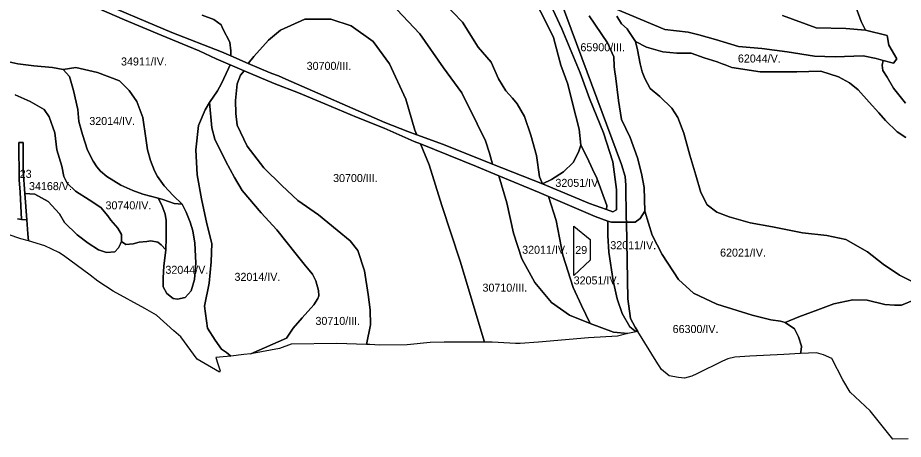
# Model space of a CAD drawing. Extents: x -521621 to -516761, y -1190184 to -1184927.
# Drawn here: x -520083 to -518423, y -1190183 to -1189393 of the extents above; entities that cross this region are included whole.
import ezdxf

# ---------------------------------------------------------------- set-up
doc = ezdxf.new("R2010")
doc.units = 0
doc.layers.add('BPEJ_s', color=7, linetype='Continuous')

msp = doc.modelspace()

# ---------------------------------------------------------------- linework, layer by layer
at = {"layer": 'BPEJ_s'}
for points in [[(-519063.9, -1189366), (-518997.4, -1189544), (-518951.2, -1189668.6), (-518944.3, -1189690.8), (-518943.5, -1189707.3), (-518942.3, -1189768.1), (-518942.1, -1189776.2), (-518970.3, -1189776.5), (-518977, -1189774.2), (-519000.8, -1189765.9), (-519088.4, -1189728.3), (-519105.4, -1189721), (-519181.4, -1189689.3), (-519222.8, -1189672.1), (-519328, -1189629.9), (-519339.7, -1189625.3), (-519396, -1189600.4), (-519447.8, -1189579.5), (-519507.3, -1189554.4), (-519556.5, -1189533.9), (-519601.9, -1189516.6), (-519658.2, -1189492.7), (-519684.5, -1189481.5), (-519711, -1189470.2), (-519742.7, -1189455.6), (-519813.9, -1189425.9), (-519882.5, -1189397.5), (-519948.9, -1189368.8)], [(-519944.2, -1189356.5), (-519794.2, -1189421.2), (-519701, -1189457.4), (-519683.6, -1189464.9), (-519650.9, -1189478.8), (-519610, -1189496.3), (-519597.8, -1189500.8), (-519594.3, -1189502.1), (-519580.6, -1189508.7), (-519394.8, -1189589.6), (-519351.9, -1189606.5), (-519335.1, -1189612.5), (-519284.9, -1189630.7), (-519192.9, -1189667.4), (-519099.2, -1189704.8), (-519011.2, -1189741.7), (-518979.4, -1189752.9), (-518967.9, -1189757), (-518960.6, -1189753.2), (-518960.6, -1189715.2), (-518967.9, -1189663.1), (-518985.2, -1189608.9), (-519011.6, -1189544.5), (-519028.8, -1189496.4), (-519062.9, -1189414.3), (-519083.6, -1189369.9)], [(-519736.9, -1189388.8), (-519715.2, -1189396.9), (-519701.7, -1189406.4), (-519698.2, -1189413.9), (-519685, -1189438.9), (-519683.3, -1189455.6), (-519683.6, -1189464.9), (-519701, -1189457.4), (-519794.2, -1189421.2), (-519944.2, -1189356.5)], [(-519383.2, -1189366.6), (-519329.3, -1189423.2), (-519284.6, -1189487.3), (-519250.7, -1189534.2), (-519222.1, -1189592.4), (-519206.5, -1189624.2), (-519198.4, -1189646.8), (-519192.9, -1189667.4), (-519284.9, -1189630.7), (-519335.1, -1189612.5), (-519338.8, -1189604.1), (-519355.5, -1189545.7), (-519386.1, -1189479.6), (-519416.7, -1189437.9), (-519457.7, -1189408.7), (-519495.9, -1189396.2), (-519544.6, -1189396.2), (-519590.1, -1189416.7), (-519612.7, -1189435.5), (-519640.2, -1189465.7), (-519650.9, -1189478.8), (-519683.6, -1189464.9), (-519683.3, -1189455.6), (-519685, -1189438.9), (-519698.2, -1189413.9), (-519701.7, -1189406.4), (-519715.2, -1189396.9), (-519736.9, -1189388.8)], [(-519285.7, -1189363.9), (-519249.6, -1189401.6), (-519220, -1189448.5), (-519195.7, -1189476.6), (-519181.7, -1189507.8), (-519168.3, -1189530.5), (-519155.7, -1189544.2), (-519146.9, -1189554.6), (-519133, -1189578.1), (-519121.4, -1189613.2), (-519110.7, -1189651.4), (-519105, -1189691.2), (-519099.2, -1189704.8), (-519192.9, -1189667.4), (-519198.4, -1189646.8), (-519206.5, -1189624.2), (-519222.1, -1189592.4), (-519250.7, -1189534.2), (-519284.6, -1189487.3), (-519329.3, -1189423.2), (-519383.2, -1189366.6)], [(-519118.6, -1189351), (-519094.8, -1189397.3), (-519078.9, -1189430.5), (-519070.3, -1189463.5), (-519065.2, -1189482), (-519052.1, -1189517.5), (-519042.9, -1189553.4), (-519030.6, -1189602), (-519027.8, -1189632.3), (-519032.2, -1189645.2), (-519041.9, -1189664.4), (-519060.3, -1189681.8), (-519082.8, -1189696.4), (-519099.2, -1189704.8), (-519105, -1189691.2), (-519110.7, -1189651.4), (-519121.4, -1189613.2), (-519133, -1189578.1), (-519146.9, -1189554.6), (-519155.7, -1189544.2), (-519168.3, -1189530.5), (-519181.7, -1189507.8), (-519195.7, -1189476.6), (-519220, -1189448.5), (-519249.6, -1189401.6), (-519285.7, -1189363.9)], [(-519083.6, -1189369.9), (-519062.9, -1189414.3), (-519028.8, -1189496.4), (-519011.6, -1189544.5), (-518985.2, -1189608.9), (-518967.9, -1189663.1), (-518960.6, -1189715.2), (-518960.6, -1189753.2), (-518967.9, -1189757), (-518979.4, -1189752.9), (-518978.8, -1189744.9), (-518997.8, -1189694.2), (-519005.4, -1189677), (-519015.4, -1189655), (-519027.8, -1189632.3), (-519030.6, -1189602), (-519042.9, -1189553.4), (-519052.1, -1189517.5), (-519065.2, -1189482), (-519070.3, -1189463.5), (-519078.9, -1189430.5), (-519094.8, -1189397.3), (-519118.6, -1189351)], [(-519011.7, -1189389.6), (-518977.5, -1189440.5), (-518965.9, -1189466.5), (-518965.2, -1189484.5), (-518963.7, -1189495), (-518962.4, -1189501.9), (-518957.2, -1189548.6), (-518951.6, -1189584.1), (-518935.3, -1189617.6), (-518921.4, -1189655.8), (-518913.8, -1189685.1), (-518909.1, -1189711.6), (-518907.7, -1189755.7), (-518916.4, -1189769.4), (-518925.9, -1189776.2), (-518942.1, -1189776.2), (-518942.3, -1189768.1), (-518943.5, -1189707.3), (-518944.3, -1189690.8), (-518951.2, -1189668.6), (-518997.4, -1189544), (-519063.9, -1189366)], [(-519948.9, -1189368.8), (-519882.5, -1189397.5), (-519813.9, -1189425.9), (-519742.7, -1189455.6), (-519711, -1189470.2), (-519684.5, -1189481.5), (-519687.6, -1189488.4), (-519700.6, -1189516.7), (-519708.6, -1189530.4), (-519723.2, -1189552), (-519731.6, -1189565.9), (-519744.1, -1189595.1), (-519748.9, -1189641), (-519746.4, -1189687.4), (-519738.3, -1189732.8), (-519728.4, -1189779.4), (-519719.1, -1189816.1), (-519720.3, -1189851), (-519723.8, -1189890.4), (-519732.6, -1189933.6), (-519727.1, -1189975), (-519712.7, -1189997.7), (-519700.6, -1190014.3), (-519691.7, -1190020.9), (-519683.2, -1190027.2), (-519704.6, -1190029.6), (-519711.8, -1190030.1), (-519707.8, -1190042.1), (-519703.4, -1190055.2), (-519704.6, -1190057.2), (-519746.2, -1190032.8), (-519777.4, -1189991.1), (-519790.1, -1189980.1), (-519822.7, -1189950.8), (-519844.4, -1189938.4), (-519903.8, -1189905.6), (-519932.9, -1189887.2), (-519947.2, -1189875.7), (-519997.2, -1189838.8), (-520005.6, -1189833.2), (-520031.8, -1189820.9), (-520062.5, -1189811.5), (-520063.8, -1189798), (-520065.7, -1189772), (-520069.3, -1189722.6), (-520050.9, -1189723.9), (-520025.9, -1189737.6), (-520004.5, -1189760.6), (-519994.8, -1189776.9), (-519971.1, -1189800), (-519950.9, -1189815.8), (-519931.7, -1189828), (-519916.7, -1189833.2), (-519900.6, -1189832), (-519894.1, -1189824.5), (-519890, -1189816.8), (-519888.1, -1189812.4), (-519880.4, -1189818), (-519866.4, -1189817.1), (-519854.9, -1189813.6), (-519840.6, -1189812.7), (-519833.1, -1189811.5), (-519820.4, -1189814), (-519813.9, -1189818.6), (-519805.2, -1189828), (-519808.9, -1189858.7), (-519810.4, -1189880.5), (-519810.1, -1189897.6), (-519803.3, -1189910.1), (-519791.5, -1189919.1), (-519783.1, -1189920.6), (-519768.8, -1189917.8), (-519757.6, -1189904.8), (-519751.4, -1189883.6), (-519748.9, -1189852.5), (-519751.1, -1189815.8), (-519754.8, -1189792.8), (-519759.8, -1189776.3), (-519766.9, -1189757.7), (-519774.4, -1189742.7), (-519791.2, -1189726.6), (-519808.6, -1189708.5), (-519821, -1189691.1), (-519826.6, -1189679.9), (-519834, -1189660.9), (-519839.3, -1189640.8), (-519842.9, -1189618.9), (-519848.2, -1189580), (-519859.4, -1189550.4), (-519874.2, -1189529.7), (-519891.9, -1189511.4), (-519933.2, -1189496.1), (-519973.9, -1189486.6), (-519997.5, -1189490.2), (-520017.4, -1189486.8), (-520052.5, -1189483.2), (-520082.7, -1189479.4), (-520099.3, -1189476.2)], [(-518962.4, -1189376.5), (-518870.1, -1189415.6), (-518826.4, -1189420.6), (-518806.4, -1189425.1), (-518775.5, -1189433.9), (-518731.9, -1189447.3), (-518688.6, -1189451.2), (-518641.1, -1189457.3), (-518590, -1189465.3), (-518550.9, -1189466.5), (-518498.4, -1189464.6), (-518473.9, -1189469.5), (-518461.2, -1189473.2), (-518462.9, -1189482), (-518461.7, -1189492), (-518453.6, -1189504.9), (-518441.5, -1189525.1), (-518419.4, -1189553.3)], [(-518649.6, -1189389.2), (-518586.3, -1189412), (-518530.9, -1189413.4), (-518494.4, -1189416.6), (-518453.6, -1189426.8), (-518450.2, -1189444.6), (-518435.2, -1189470.3), (-518441.7, -1189478.7), (-518461.2, -1189473.2), (-518473.9, -1189469.5), (-518498.4, -1189464.6), (-518550.9, -1189466.5), (-518590, -1189465.3), (-518641.1, -1189457.3), (-518688.6, -1189451.2), (-518731.9, -1189447.3), (-518775.5, -1189433.9), (-518806.4, -1189425.1), (-518826.4, -1189420.6), (-518870.1, -1189415.6), (-518962.4, -1189376.5)], [(-518514, -1189368), (-518502.4, -1189400.1), (-518494.4, -1189416.6), (-518530.9, -1189413.4), (-518586.3, -1189412), (-518649.6, -1189389.2)], [(-518494.4, -1189416.6), (-518502.4, -1189400.1), (-518514, -1189368)], [(-518402, -1189922.2), (-518426.9, -1189931.6), (-518439.7, -1189932.1), (-518458.2, -1189930.4), (-518491.2, -1189922.6), (-518517.8, -1189921.8), (-518553.4, -1189929.1), (-518583.4, -1189940.7), (-518619, -1189954), (-518644.7, -1189964.4), (-518653.5, -1189962.1), (-518671.8, -1189959.1), (-518706.5, -1189950.9), (-518772.5, -1189930.3), (-518816.6, -1189909.1), (-518844.3, -1189883.7), (-518874.9, -1189837.2), (-518894.1, -1189800.7), (-518907.7, -1189755.7), (-518909.1, -1189711.6), (-518913.8, -1189685.1), (-518921.4, -1189655.8), (-518935.3, -1189617.6), (-518951.6, -1189584.1), (-518957.2, -1189548.6), (-518962.4, -1189501.9), (-518963.7, -1189495), (-518965.2, -1189484.5), (-518965.9, -1189466.5), (-518977.5, -1189440.5), (-519011.7, -1189389.6)], [(-518418.5, -1189617.8), (-518435.1, -1189606.9), (-518456.4, -1189585.6), (-518468.9, -1189571.5), (-518487.4, -1189551.7), (-518508, -1189528.3), (-518524.1, -1189515), (-518544.7, -1189504.1), (-518577.7, -1189493.7), (-518622.8, -1189494.5), (-518691.7, -1189494.5), (-518744.5, -1189486.8), (-518757.4, -1189481.6), (-518762.5, -1189479.5), (-518771.9, -1189476.2), (-518796.7, -1189468.3), (-518820.9, -1189460), (-518847.6, -1189460), (-518873.9, -1189457.1), (-518904.6, -1189448.4), (-518925.2, -1189438), (-518937.4, -1189419.2), (-518941, -1189413.8), (-518951.1, -1189404.8), (-518960.1, -1189390.3)], [(-518960.1, -1189390.3), (-518951.1, -1189404.8), (-518941, -1189413.8), (-518937.4, -1189419.2), (-518925.2, -1189438), (-518921.2, -1189453.5), (-518916.5, -1189479.5), (-518912.7, -1189494.4), (-518907.9, -1189506.9), (-518897.6, -1189526.2), (-518879.6, -1189541.2), (-518857.3, -1189562.7), (-518845.8, -1189580.3), (-518834.6, -1189609.9), (-518823, -1189650.6), (-518812.3, -1189688), (-518802.9, -1189721), (-518790.9, -1189744.2), (-518772.9, -1189757.9), (-518749.3, -1189766.5), (-518710.3, -1189777.6), (-518668.7, -1189784.9), (-518612.1, -1189796.1), (-518566.6, -1189801.2), (-518531.1, -1189808.9), (-518490.3, -1189831.7), (-518461.2, -1189855.3), (-518430.3, -1189875.9), (-518397.7, -1189892.2)], [(-518461.2, -1189473.2), (-518441.7, -1189478.7), (-518435.2, -1189470.3), (-518450.2, -1189444.6), (-518453.6, -1189426.8), (-518494.4, -1189416.6)], [(-518397.7, -1189892.2), (-518430.3, -1189875.9), (-518461.2, -1189855.3), (-518490.3, -1189831.7), (-518531.1, -1189808.9), (-518566.6, -1189801.2), (-518612.1, -1189796.1), (-518668.7, -1189784.9), (-518710.3, -1189777.6), (-518749.3, -1189766.5), (-518772.9, -1189757.9), (-518790.9, -1189744.2), (-518802.9, -1189721), (-518812.3, -1189688), (-518823, -1189650.6), (-518834.6, -1189609.9), (-518845.8, -1189580.3), (-518857.3, -1189562.7), (-518879.6, -1189541.2), (-518897.6, -1189526.2), (-518907.9, -1189506.9), (-518912.7, -1189494.4), (-518916.5, -1189479.5), (-518921.2, -1189453.5), (-518925.2, -1189438)], [(-518925.2, -1189438), (-518904.6, -1189448.4), (-518873.9, -1189457.1), (-518847.6, -1189460), (-518820.9, -1189460), (-518796.7, -1189468.3), (-518771.9, -1189476.2), (-518762.5, -1189479.5), (-518757.4, -1189481.6), (-518744.5, -1189486.8), (-518691.7, -1189494.5), (-518622.8, -1189494.5), (-518577.7, -1189493.7), (-518544.7, -1189504.1), (-518524.1, -1189515), (-518508, -1189528.3), (-518487.4, -1189551.7), (-518468.9, -1189571.5), (-518456.4, -1189585.6), (-518435.1, -1189606.9), (-518418.5, -1189617.8)], [(-520099.3, -1189476.2), (-520082.7, -1189479.4), (-520052.5, -1189483.2), (-520017.4, -1189486.8), (-519997.5, -1189490.2), (-519985.7, -1189503.2), (-519978.1, -1189529.7), (-519970.4, -1189565.2), (-519968, -1189587.6), (-519961.5, -1189611.9), (-519952.1, -1189641.4), (-519941.5, -1189662.1), (-519934.4, -1189672.7), (-519927.9, -1189681.1), (-519915.5, -1189691.1), (-519889.4, -1189707.3), (-519867, -1189717.2), (-519848.4, -1189724.1), (-519819.8, -1189731.5), (-519812.9, -1189744.6), (-519806.7, -1189761.4), (-519804.5, -1189773.5), (-519804.8, -1189805.6), (-519805.2, -1189828), (-519813.9, -1189818.6), (-519820.4, -1189814), (-519833.1, -1189811.5), (-519840.6, -1189812.7), (-519854.9, -1189813.6), (-519866.4, -1189817.1), (-519880.4, -1189818), (-519888.1, -1189812.4), (-519888.5, -1189799.3), (-519895, -1189787.5), (-519908, -1189772.6), (-519913.6, -1189764.5), (-519927.3, -1189749), (-519949.1, -1189734.6), (-519974.6, -1189718.5), (-519990.1, -1189703.5), (-519996.3, -1189691.1), (-520000.2, -1189671.7), (-520009.4, -1189641.1), (-520013.1, -1189608.8), (-520023.7, -1189579.3), (-520033.2, -1189565.3), (-520059.4, -1189550.3), (-520087.7, -1189537.8)], [(-518419.4, -1189553.3), (-518441.5, -1189525.1), (-518453.6, -1189504.9), (-518461.7, -1189492), (-518462.9, -1189482), (-518461.2, -1189473.2)], [(-520087.7, -1189537.8), (-520059.4, -1189550.3), (-520033.2, -1189565.3), (-520023.7, -1189579.3), (-520013.1, -1189608.8), (-520009.4, -1189641.1), (-520000.2, -1189671.7), (-519996.3, -1189691.1), (-519990.1, -1189703.5), (-519974.6, -1189718.5), (-519949.1, -1189734.6), (-519927.3, -1189749), (-519913.6, -1189764.5), (-519908, -1189772.6), (-519895, -1189787.5), (-519888.5, -1189799.3), (-519888.1, -1189812.4), (-519890, -1189816.8), (-519894.1, -1189824.5), (-519900.6, -1189832), (-519916.7, -1189833.2), (-519931.7, -1189828), (-519950.9, -1189815.8), (-519971.1, -1189800), (-519994.8, -1189776.9), (-520004.5, -1189760.6), (-520025.9, -1189737.6), (-520050.9, -1189723.9), (-520069.3, -1189722.6), (-520072.5, -1189680.1), (-520072.7, -1189627.3), (-520080.9, -1189627.3), (-520079.8, -1189697.2), (-520078, -1189720.3), (-520075.6, -1189771.2), (-520083.1, -1189770.3)], [(-520083.1, -1189770.3), (-520075.6, -1189771.2), (-520065.7, -1189772), (-520063.8, -1189798), (-520062.5, -1189811.5), (-520077, -1189807.4), (-520100.5, -1189799.2)], [(-518414.2, -1190182.6), (-518442.7, -1190183.2), (-518452.6, -1190170.5), (-518485.5, -1190130), (-518522.6, -1190094.8), (-518536.6, -1190071.9), (-518557, -1190031.8), (-518572.8, -1190024.7), (-518586, -1190021.3), (-518616.2, -1190022.7), (-518614.7, -1190015.7), (-518614.1, -1190008.6), (-518619.4, -1189991), (-518627, -1189976.2), (-518644.7, -1189964.4), (-518619, -1189954), (-518583.4, -1189940.7), (-518553.4, -1189929.1), (-518517.8, -1189921.8), (-518491.2, -1189922.6), (-518458.2, -1189930.4), (-518439.7, -1189932.1), (-518426.9, -1189931.6), (-518402, -1189922.2)]]:
    msp.add_lwpolyline(points, dxfattribs=at)
for points in [[(-519650.9, -1189478.8), (-519640.2, -1189465.7), (-519612.7, -1189435.5), (-519590.1, -1189416.7), (-519544.6, -1189396.2), (-519495.9, -1189396.2), (-519457.7, -1189408.7), (-519416.7, -1189437.9), (-519386.1, -1189479.6), (-519355.5, -1189545.7), (-519338.8, -1189604.1), (-519335.1, -1189612.5), (-519351.9, -1189606.5), (-519394.8, -1189589.6), (-519580.6, -1189508.7), (-519594.3, -1189502.1), (-519597.8, -1189500.8), (-519610, -1189496.3)], [(-519723.2, -1189552), (-519708.6, -1189530.4), (-519700.6, -1189516.7), (-519687.6, -1189488.4), (-519684.5, -1189481.5), (-519658.2, -1189492.7), (-519665.5, -1189501.2), (-519671.8, -1189517.2), (-519674.6, -1189548.1), (-519673.9, -1189572.5), (-519671.4, -1189594.7), (-519653, -1189634), (-519621.7, -1189674.4), (-519587.7, -1189707.8), (-519558.1, -1189735.6), (-519519.3, -1189762.4), (-519483.9, -1189791.3), (-519459.9, -1189811.5), (-519445.7, -1189829.6), (-519433.1, -1189867.8), (-519426, -1189912), (-519422.2, -1189940.9), (-519421.5, -1189969), (-519429, -1190005.6), (-519484.8, -1190003.9), (-519570.6, -1190005), (-519592.2, -1190013.2), (-519642.9, -1190022.7), (-519646.2, -1190023.1), (-519579.3, -1189993.7), (-519566.3, -1189975), (-519549.7, -1189955.7), (-519528.1, -1189931.4), (-519520.4, -1189919.7), (-519518.7, -1189914.2), (-519519.3, -1189904.3), (-519524.3, -1189886), (-519530.3, -1189873.8), (-519543.3, -1189858.5), (-519560.8, -1189836.1), (-519597.4, -1189790.8), (-519626.3, -1189758.6), (-519662.1, -1189716.8), (-519676.7, -1189692.5), (-519692.6, -1189662.6), (-519713.5, -1189620.8), (-519719.1, -1189599.3)], [(-519997.5, -1189490.2), (-519973.9, -1189486.6), (-519933.2, -1189496.1), (-519891.9, -1189511.4), (-519874.2, -1189529.7), (-519859.4, -1189550.4), (-519848.2, -1189580), (-519842.9, -1189618.9), (-519839.3, -1189640.8), (-519834, -1189660.9), (-519826.6, -1189679.9), (-519821, -1189691.1), (-519808.6, -1189708.5), (-519791.2, -1189726.6), (-519774.4, -1189742.7), (-519789.3, -1189741.5), (-519811.1, -1189734), (-519819.8, -1189731.5), (-519848.4, -1189724.1), (-519867, -1189717.2), (-519889.4, -1189707.3), (-519915.5, -1189691.1), (-519927.9, -1189681.1), (-519934.4, -1189672.7), (-519941.5, -1189662.1), (-519952.1, -1189641.4), (-519961.5, -1189611.9), (-519968, -1189587.6), (-519970.4, -1189565.2), (-519978.1, -1189529.7), (-519985.7, -1189503.2)], [(-519658.2, -1189492.7), (-519601.9, -1189516.6), (-519556.5, -1189533.9), (-519507.3, -1189554.4), (-519447.8, -1189579.5), (-519396, -1189600.4), (-519339.7, -1189625.3), (-519328, -1189629.9), (-519311.7, -1189668.8), (-519288, -1189744.9), (-519253.6, -1189849.2), (-519208.1, -1190001.4), (-519262.1, -1190001.2), (-519283.6, -1190001.2), (-519310, -1190002), (-519352.8, -1190006.3), (-519404.5, -1190006.9), (-519423, -1190005.8), (-519429, -1190005.6), (-519421.5, -1189969), (-519422.2, -1189940.9), (-519426, -1189912), (-519433.1, -1189867.8), (-519445.7, -1189829.6), (-519459.9, -1189811.5), (-519483.9, -1189791.3), (-519519.3, -1189762.4), (-519558.1, -1189735.6), (-519587.7, -1189707.8), (-519621.7, -1189674.4), (-519653, -1189634), (-519671.4, -1189594.7), (-519673.9, -1189572.5), (-519674.6, -1189548.1), (-519671.8, -1189517.2), (-519665.5, -1189501.2)], [(-519723.2, -1189552), (-519719.1, -1189599.3), (-519713.5, -1189620.8), (-519692.6, -1189662.6), (-519676.7, -1189692.5), (-519662.1, -1189716.8), (-519626.3, -1189758.6), (-519597.4, -1189790.8), (-519560.8, -1189836.1), (-519543.3, -1189858.5), (-519530.3, -1189873.8), (-519524.3, -1189886), (-519519.3, -1189904.3), (-519518.7, -1189914.2), (-519520.4, -1189919.7), (-519528.1, -1189931.4), (-519549.7, -1189955.7), (-519566.3, -1189975), (-519579.3, -1189993.7), (-519646.2, -1190023.1), (-519658.8, -1190024.5), (-519683.2, -1190027.2), (-519691.7, -1190020.9), (-519700.6, -1190014.3), (-519712.7, -1189997.7), (-519727.1, -1189975), (-519732.6, -1189933.6), (-519723.8, -1189890.4), (-519720.3, -1189851), (-519719.1, -1189816.1), (-519728.4, -1189779.4), (-519738.3, -1189732.8), (-519746.4, -1189687.4), (-519748.9, -1189641), (-519744.1, -1189595.1), (-519731.6, -1189565.9)], [(-520075.6, -1189771.2), (-520078, -1189720.3), (-520079.8, -1189697.2), (-520080.9, -1189627.3), (-520072.7, -1189627.3), (-520072.5, -1189680.1), (-520069.3, -1189722.6), (-520065.7, -1189772)], [(-519208.1, -1190001.4), (-519253.6, -1189849.2), (-519288, -1189744.9), (-519311.7, -1189668.8), (-519328, -1189629.9), (-519222.8, -1189672.1), (-519181.4, -1189689.3), (-519166.5, -1189740), (-519153.9, -1189796.8), (-519138.1, -1189845), (-519114, -1189889.7), (-519082.6, -1189926.6), (-519049.1, -1189950.7), (-519010.3, -1189966), (-518966.1, -1189982.7), (-518939.7, -1189985.2), (-518959.1, -1189990.1), (-519013.1, -1189993.1), (-519106.8, -1190001), (-519141.4, -1190003.5), (-519150.2, -1190003.5), (-519160.7, -1190003), (-519193.8, -1190001.4)], [(-519099.2, -1189704.8), (-519082.8, -1189696.4), (-519060.3, -1189681.8), (-519041.9, -1189664.4), (-519032.2, -1189645.2), (-519027.8, -1189632.3), (-519015.4, -1189655), (-519005.4, -1189677), (-518997.8, -1189694.2), (-518978.8, -1189744.9), (-518979.4, -1189752.9), (-519011.2, -1189741.7)], [(-519181.4, -1189689.3), (-519105.4, -1189721), (-519088.4, -1189728.3), (-519073.6, -1189773.1), (-519061.2, -1189838.5), (-519041.9, -1189898.8), (-519026.1, -1189932.6), (-519010.3, -1189966), (-519049.1, -1189950.7), (-519082.6, -1189926.6), (-519114, -1189889.7), (-519138.1, -1189845), (-519153.9, -1189796.8), (-519166.5, -1189740)], [(-519819.8, -1189731.5), (-519811.1, -1189734), (-519789.3, -1189741.5), (-519774.4, -1189742.7), (-519766.9, -1189757.7), (-519759.8, -1189776.3), (-519754.8, -1189792.8), (-519751.1, -1189815.8), (-519748.9, -1189852.5), (-519751.4, -1189883.6), (-519757.6, -1189904.8), (-519768.8, -1189917.8), (-519783.1, -1189920.6), (-519791.5, -1189919.1), (-519803.3, -1189910.1), (-519810.1, -1189897.6), (-519810.4, -1189880.5), (-519808.9, -1189858.7), (-519805.2, -1189828), (-519804.8, -1189805.6), (-519804.5, -1189773.5), (-519806.7, -1189761.4), (-519812.9, -1189744.6)], [(-519088.4, -1189728.3), (-519000.8, -1189765.9), (-518977, -1189774.2), (-518976.7, -1189801.2), (-518975, -1189832.4), (-518967, -1189886.3), (-518959.7, -1189920.2), (-518949.8, -1189947.8), (-518935.6, -1189972.4), (-518926.2, -1189979.8), (-518920.9, -1189981.4), (-518939.7, -1189985.2), (-518966.1, -1189982.7), (-519010.3, -1189966), (-519026.1, -1189932.6), (-519041.9, -1189898.8), (-519061.2, -1189838.5), (-519073.6, -1189773.1)], [(-518942.1, -1189776.2), (-518925.9, -1189776.2), (-518916.4, -1189769.4), (-518907.7, -1189755.7), (-518894.1, -1189800.7), (-518874.9, -1189837.2), (-518844.3, -1189883.7), (-518816.6, -1189909.1), (-518772.5, -1189930.3), (-518706.5, -1189950.9), (-518671.8, -1189959.1), (-518653.5, -1189962.1), (-518644.7, -1189964.4), (-518627, -1189976.2), (-518619.4, -1189991), (-518614.1, -1190008.6), (-518614.7, -1190015.7), (-518616.2, -1190022.7), (-518647, -1190024.2), (-518711.1, -1190027.2), (-518738.7, -1190029.2), (-518752, -1190032.3), (-518762.2, -1190037), (-518810.3, -1190060.8), (-518819.6, -1190065), (-518833.4, -1190068.5), (-518844.8, -1190067.3), (-518862.2, -1190064.2), (-518876.2, -1190052.7), (-518886.5, -1190036.6), (-518920.9, -1189981.4), (-518925.9, -1189973.4), (-518934.5, -1189956.8), (-518939.3, -1189919.9)], [(-518977, -1189774.2), (-518970.3, -1189776.5), (-518942.1, -1189776.2), (-518939.3, -1189919.9), (-518934.5, -1189956.8), (-518925.9, -1189973.4), (-518920.9, -1189981.4), (-518926.2, -1189979.8), (-518935.6, -1189972.4), (-518949.8, -1189947.8), (-518959.7, -1189920.2), (-518967, -1189886.3), (-518975, -1189832.4), (-518976.7, -1189801.2)], [(-519010.1, -1189809), (-519010.1, -1189847.4), (-519040.4, -1189876.1), (-519040.7, -1189784.1)], [(-519010.1, -1189809), (-519010.1, -1189847.4), (-519040.4, -1189876.1), (-519040.7, -1189784.1)]]:
    msp.add_lwpolyline(points, close=True, dxfattribs=at)

# ---------------------------------------------------------------- texts
for s, p in [('65900/III.', (-519028.3, -1189456.1)), ('34911/IV.', (-519889.2, -1189482.8)), ('62044/V.', (-518733.2, -1189477.2)), ('30700/III.', (-519541.3, -1189491)), ('32014/IV.', (-519948.6, -1189594.3)), ('23', (-520079, -1189693.3)), ('30700/III.', (-519491.8, -1189701.2)), ('32051/IV.', (-519075.2, -1189710.2)), ('34168/V.', (-520061.6, -1189716.3)), ('30740/IV.', (-519918.2, -1189752.3)), ('32011/IV.', (-518972.3, -1189827)), ('32011/IV.', (-519137.5, -1189835.6)), ('29', (-519038, -1189836)), ('62021/IV.', (-518766.6, -1189840.9)), ('32044/V.', (-519806, -1189873.1)), ('32014/IV.', (-519676.5, -1189886.3)), ('32051/IV.', (-519041, -1189893)), ('30710/III.', (-519211.8, -1189906.6)), ('30710/III.', (-519524.8, -1189968.9)), ('66300/IV.', (-518855.5, -1189984.1))]:
    msp.add_text(s, height=15, dxfattribs=at).set_placement(p)

doc.saveas('drawing.dxf')
